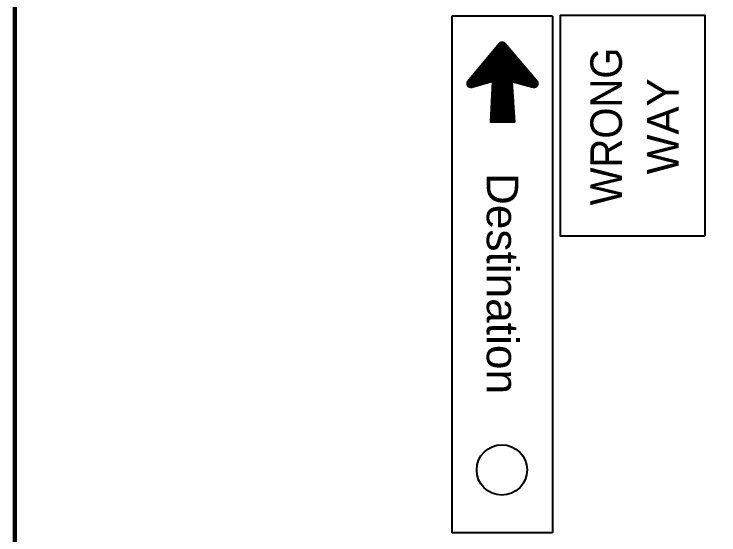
# Model space of a CAD drawing. Extents: x -198 to 658, y -402 to 142.
# Drawn here: x -140.5 to -76, y -213 to -165.3 of the extents above; entities that cross this region are included whole.
import ezdxf
from ezdxf.enums import TextEntityAlignment as Align

# ---------------------------------------------------------------- set-up
doc = ezdxf.new("R2010")
doc.units = 0
doc.header["$LTSCALE"] = 0.96
doc.layers.add('1', color=7, linetype='Continuous', lineweight=35)

msp = doc.modelspace()

# ---------------------------------------------------------------- linework, layer by layer
at = {"layer": '1', "lineweight": 40}
for p, q in [((-100.4444, -165.55), (-100.4444, -212.782)), ((-91.2284, -165.55), (-100.4444, -165.55)), ((-91.2284, -165.55), (-91.2284, -212.782)), ((-95.4284, -168.214), (-96.2684, -168.214)), ((-95.7884, -168.214), (-96.2684, -168.214)), ((-95.5004, -168.094), (-96.1724, -168.094)), ((-95.7884, -168.094), (-96.1724, -168.094)), ((-94.8524, -168.886), (-96.8444, -168.886)), ((-95.7884, -168.886), (-96.8444, -168.886)), ((-94.9244, -168.79), (-96.7244, -168.79)), ((-95.7884, -168.79), (-96.7244, -168.79)), ((-95.0204, -168.67), (-96.6284, -168.67)), ((-95.7884, -168.67), (-96.6284, -168.67)), ((-95.1164, -168.55), (-96.5564, -168.55)), ((-95.7884, -168.55), (-96.5564, -168.55)), ((-95.2124, -168.43), (-96.4364, -168.43)), ((-95.7884, -168.43), (-96.4364, -168.43)), ((-95.3084, -168.31), (-96.3404, -168.31)), ((-95.7884, -168.31), (-96.3404, -168.31)), ((-94.3484, -169.462), (-97.3004, -169.462)), ((-95.7884, -169.462), (-97.3004, -169.462)), ((-94.4444, -169.366), (-97.2044, -169.366)), ((-95.7884, -169.366), (-97.2044, -169.366)), ((-94.5644, -169.246), (-97.1084, -169.246)), ((-95.7884, -169.246), (-97.1084, -169.246)), ((-94.6364, -169.126), (-97.0124, -169.126)), ((-95.7884, -169.126), (-97.0124, -169.126)), ((-94.7564, -169.006), (-96.9164, -169.006)), ((-95.7884, -169.006), (-96.9164, -169.006)), ((-93.7724, -170.158), (-97.8764, -170.158)), ((-95.7884, -170.158), (-97.8764, -170.158)), ((-93.8684, -170.038), (-97.7804, -170.038)), ((-95.7884, -170.038), (-97.7804, -170.038)), ((-93.9644, -169.942), (-97.6844, -169.942)), ((-95.7884, -169.942), (-97.6844, -169.942)), ((-94.0604, -169.822), (-97.5884, -169.822)), ((-95.7884, -169.822), (-97.5884, -169.822)), ((-94.1564, -169.702), (-97.4924, -169.702)), ((-95.7884, -169.702), (-97.4924, -169.702)), ((-94.2524, -169.582), (-97.3964, -169.582)), ((-95.7884, -169.582), (-97.3964, -169.582)), ((-93.2924, -170.734), (-98.3564, -170.734)), ((-95.7884, -170.734), (-98.3564, -170.734)), ((-93.3884, -170.614), (-98.2604, -170.614)), ((-95.7884, -170.614), (-98.2604, -170.614)), ((-93.4844, -170.518), (-98.1644, -170.518)), ((-95.7884, -170.518), (-98.1644, -170.518)), ((-93.5804, -170.398), (-98.0684, -170.398)), ((-95.7884, -170.398), (-98.0684, -170.398)), ((-93.6764, -170.278), (-97.9724, -170.278)), ((-95.7884, -170.278), (-97.9724, -170.278)), ((-92.6924, -171.43), (-98.9084, -171.43)), ((-95.7884, -171.43), (-98.9084, -171.43)), ((-92.7884, -171.31), (-98.8364, -171.31)), ((-95.7884, -171.31), (-98.8364, -171.31)), ((-92.8844, -171.19), (-98.7404, -171.19)), ((-95.7884, -171.19), (-98.7404, -171.19)), ((-92.9804, -171.094), (-98.6444, -171.094)), ((-95.7884, -171.094), (-98.6444, -171.094)), ((-93.1004, -170.974), (-98.5484, -170.974)), ((-95.7884, -170.974), (-98.5484, -170.974)), ((-93.1724, -170.854), (-98.4524, -170.854)), ((-95.7884, -170.854), (-98.4524, -170.854)), ((-97.1804, -171.67), (-99.0524, -171.67)), ((-97.1804, -171.67), (-99.0524, -171.67)), ((-97.6124, -171.766), (-99.0524, -171.766)), ((-97.6124, -171.766), (-99.0524, -171.766)), ((-94.9004, -171.766), (-96.7484, -171.766)), ((-95.7884, -171.766), (-96.7484, -171.766)), ((-94.9004, -171.886), (-96.7484, -171.886)), ((-95.7884, -171.886), (-96.7484, -171.886)), ((-94.8764, -172.006), (-96.7484, -172.006)), ((-95.7884, -172.006), (-96.7484, -172.006)), ((-94.8764, -172.126), (-96.7484, -172.126)), ((-95.7884, -172.126), (-96.7484, -172.126)), ((-95.7884, -171.55), (-96.7244, -171.55)), ((-94.9004, -171.67), (-96.7244, -171.67)), ((-95.7884, -171.67), (-96.7244, -171.67)), ((-92.5724, -171.67), (-94.4924, -171.67)), ((-92.6204, -171.886), (-93.6284, -171.886)), ((-94.8524, -172.702), (-96.7964, -172.702)), ((-95.7884, -172.702), (-96.7964, -172.702)), ((-94.8764, -172.246), (-96.7724, -172.246)), ((-95.7884, -172.246), (-96.7724, -172.246)), ((-94.8764, -172.342), (-96.7724, -172.342)), ((-95.7884, -172.342), (-96.7724, -172.342)), ((-94.8764, -172.462), (-96.7724, -172.462)), ((-95.7884, -172.462), (-96.7724, -172.462)), ((-94.8524, -172.582), (-96.7724, -172.582)), ((-95.7884, -172.582), (-96.7724, -172.582)), ((-94.8284, -173.158), (-96.8204, -173.158)), ((-95.7884, -173.158), (-96.8204, -173.158)), ((-94.8284, -173.278), (-96.8204, -173.278)), ((-95.7884, -173.278), (-96.8204, -173.278)), ((-94.8044, -173.398), (-96.8204, -173.398)), ((-95.7884, -173.398), (-96.8204, -173.398)), ((-94.8524, -172.822), (-96.7964, -172.822)), ((-95.7884, -172.822), (-96.7964, -172.822)), ((-94.8524, -172.918), (-96.7964, -172.918)), ((-95.7884, -172.918), (-96.7964, -172.918)), ((-94.8284, -173.038), (-96.7964, -173.038)), ((-95.7884, -173.038), (-96.7964, -173.038)), ((-94.7804, -173.974), (-96.8684, -173.974)), ((-95.7884, -173.974), (-96.8684, -173.974)), ((-94.8044, -173.494), (-96.8444, -173.494)), ((-95.7884, -173.494), (-96.8444, -173.494)), ((-94.8044, -173.614), (-96.8444, -173.614)), ((-95.7884, -173.614), (-96.8444, -173.614)), ((-94.8044, -173.734), (-96.8444, -173.734)), ((-95.7884, -173.734), (-96.8444, -173.734)), ((-94.7804, -173.854), (-96.8444, -173.854)), ((-95.7884, -173.854), (-96.8444, -173.854)), ((-94.7564, -174.43), (-96.8924, -174.43)), ((-95.7884, -174.43), (-96.8924, -174.43)), ((-94.7324, -174.55), (-96.8924, -174.55)), ((-95.7884, -174.55), (-96.8924, -174.55)), ((-94.7324, -174.646), (-96.8924, -174.646)), ((-95.7884, -174.646), (-96.8924, -174.646)), ((-94.7804, -174.07), (-96.8684, -174.07)), ((-95.7884, -174.07), (-96.8684, -174.07)), ((-94.7564, -174.19), (-96.8684, -174.19)), ((-95.7884, -174.19), (-96.8684, -174.19)), ((-94.7564, -174.31), (-96.8684, -174.31)), ((-95.7884, -174.31), (-96.8684, -174.31)), ((-94.7084, -175.126), (-96.9164, -175.126)), ((-95.7884, -175.126), (-96.9164, -175.126)), ((-94.6844, -175.222), (-96.9164, -175.222)), ((-95.7884, -175.222), (-96.9164, -175.222)), ((-94.7324, -174.766), (-96.8924, -174.766)), ((-95.7884, -174.766), (-96.8924, -174.766)), ((-94.7084, -174.886), (-96.8924, -174.886)), ((-95.7884, -174.886), (-96.8924, -174.886)), ((-94.7084, -175.006), (-96.8924, -175.006)), ((-95.7884, -175.006), (-96.8924, -175.006)), ((-91.2284, -212.782), (-100.4444, -212.782))]:
    msp.add_line(p, q, dxfattribs=at)
at = {"layer": '1'}
for p, q in [((-98.9804, -171.478), (-96.1244, -168.022)), ((-95.5724, -168.022), (-92.6444, -171.478))]:
    msp.add_line(p, q, dxfattribs=at)
at = {"layer": '1', "lineweight": 158}
msp.add_lwpolyline([(651.2125, 135.4296), (-140.4875, 135.3296), (-140.3875, -390.6704)], dxfattribs=at)
at = {"layer": '1', "lineweight": 40}
msp.add_lwpolyline([(-77.2844, -185.638), (-77.2844, -165.478), (-90.5324, -165.478), (-90.5324, -185.638)], close=True, dxfattribs=at)
for points in [[(-95.7884, -167.974), (-96.0284, -167.974), (-96.0524, -167.974)], [(-95.6444, -167.974), (-95.6204, -167.974), (-95.6444, -167.974), (-96.0284, -167.974), (-96.0284, -167.974)], [(-96.7724, -171.55), (-99.0044, -171.55), (-99.0044, -171.55)], [(-96.7724, -171.55), (-99.0044, -171.55), (-99.0044, -171.55)], [(-98.0204, -171.886), (-99.0044, -171.886), (-99.0044, -171.886)], [(-98.0204, -171.886), (-99.0044, -171.886), (-99.0044, -171.886)], [(-98.4284, -172.006), (-98.9084, -172.006), (-98.9084, -172.006)], [(-98.4284, -172.006), (-98.9084, -172.006), (-98.9084, -172.006)], [(-92.5964, -171.55), (-92.6204, -171.55), (-94.9244, -171.55), (-96.7244, -171.55)], [(-92.5724, -171.766), (-92.5724, -171.766), (-94.0604, -171.766)], [(-92.7164, -172.006), (-92.7404, -172.006), (-93.1964, -172.006)]]:
    msp.add_lwpolyline(points, dxfattribs=at)
at = {"layer": '1'}
msp.add_lwpolyline([(-93.0284, -172.054), (-94.9244, -171.55), (-94.6844, -175.222), (-96.9164, -175.222), (-96.7244, -171.526), (-98.6204, -172.054)], dxfattribs=at)
at = {"layer": '1', "lineweight": 40}
msp.add_circle((-95.8728, -207.0411), 2.304, dxfattribs=at)
at = {"layer": '1'}
for centre, start, end in [((-95.844, -168.2594), 40.25653, 140.40471), ((-92.924, -171.7063), 255.11373, 40.25762), ((-98.7, -171.7105), 140.43005, 285.55122)]:
    msp.add_arc(centre, 0.3571, start, end, dxfattribs=at)

# ---------------------------------------------------------------- texts
for s, rotation, width, p in [('WRONG', 90, 0.95, (-84.8924, -175.6226)), ('Destination', 270, 1.05, (-97.2524, -189.9873))]:
    msp.add_text(s, height=2.88, rotation=rotation, dxfattribs=dict(at, width=width)).set_placement(p, align=Align.CENTER)
msp.add_text('WAY', height=2.88, rotation=90, dxfattribs=at).set_placement((-79.7084, -175.616), align=Align.CENTER)

doc.saveas('drawing.dxf')
